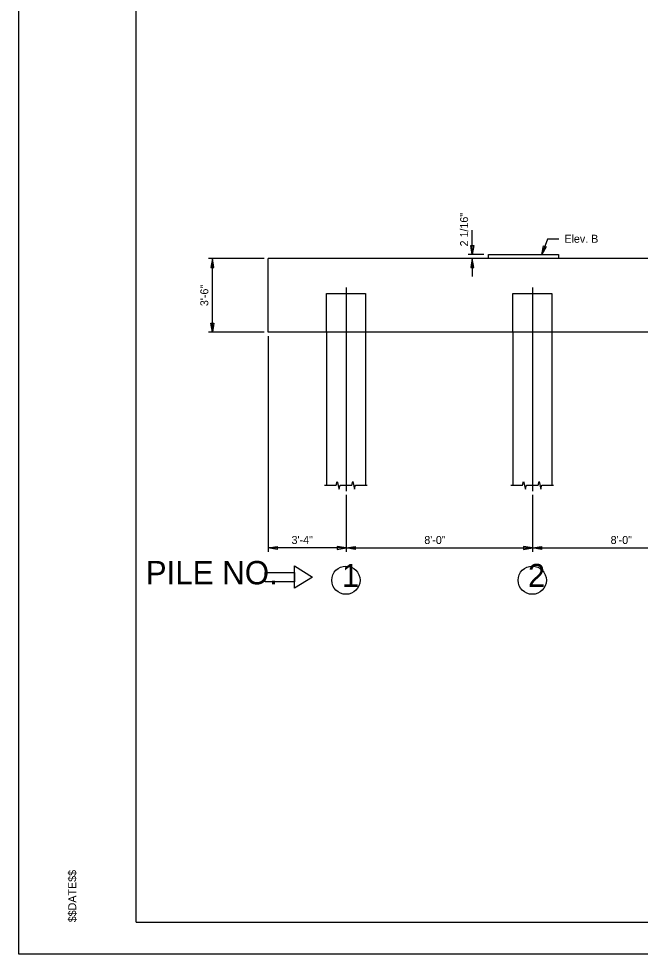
# Model space of a CAD drawing. Extents: x 437 to 537, y 571 to 720.
# Drawn here: x 437.19 to 463.88, y 654.41 to 694.6 of the extents above; entities that cross this region are included whole.
import ezdxf

# ---------------------------------------------------------------- set-up
doc = ezdxf.new("R2010")
doc.units = 0
for name, color, linetype in [('BR_AUTO DIMENSION', 7, 'Continuous'), ('BR_BORDER LINES', 7, 'Continuous'), ('BR_CENTER LINES', 7, 'Continuous'), ('BR_CONCRETE', 7, 'Continuous'), ('BR_PRESTRESSED BEAM', 7, 'Continuous'), ('BR_TABLE LINES', 7, 'Continuous'), ('BR_TEXT', 7, 'Continuous'), ('RD_SHT_IplotShp', 7, 'Continuous')]:
    doc.layers.add(name, color=color, linetype=linetype)

msp = doc.modelspace()

# ---------------------------------------------------------------- linework, layer by layer
at = {"layer": 'BR_AUTO DIMENSION'}
for p, q in [((456.66, 684.46), (456.66, 685.506)), ((456.66, 684.46), (456.595, 684.847)), ((456.595, 684.847), (456.724, 684.847)), ((456.724, 684.847), (456.66, 684.46)), ((459.897, 685.132), (459.646, 684.46)), ((459.646, 684.46), (459.721, 684.845)), ((459.721, 684.845), (459.841, 684.8)), ((460.376, 685.132), (459.897, 685.132)), ((457.157, 684.46), (456.488, 684.46)), ((459.841, 684.8), (459.646, 684.46)), ((447.732, 684.293), (445.331, 684.293)), ((445.503, 684.293), (445.438, 683.907)), ((445.503, 681.127), (445.503, 684.293)), ((445.567, 683.906), (445.503, 684.293)), ((456.66, 684.293), (456.595, 683.907)), ((456.66, 684.293), (456.66, 683.523)), ((456.724, 683.906), (456.66, 684.293)), ((445.438, 683.907), (445.567, 683.906)), ((456.595, 683.907), (456.724, 683.906)), ((445.438, 681.513), (445.567, 681.514)), ((445.503, 681.127), (445.438, 681.513)), ((445.567, 681.514), (445.503, 681.127)), ((447.732, 681.127), (445.331, 681.127)), ((447.904, 680.955), (447.904, 671.689)), ((451.242, 674.146), (451.242, 671.689)), ((459.242, 674.146), (459.242, 671.689)), ((451.242, 672.377), (451.242, 671.689)), ((447.904, 671.861), (448.291, 671.925)), ((451.237, 671.861), (447.904, 671.861)), ((448.291, 671.796), (447.904, 671.861)), ((448.291, 671.925), (448.291, 671.796)), ((451.242, 671.861), (450.855, 671.925)), ((450.855, 671.925), (450.855, 671.796)), ((450.855, 671.796), (451.242, 671.861)), ((451.237, 671.861), (459.237, 671.861)), ((451.242, 671.861), (451.629, 671.925)), ((451.629, 671.796), (451.242, 671.861)), ((451.629, 671.925), (451.629, 671.796)), ((459.242, 671.861), (458.855, 671.925)), ((458.855, 671.925), (458.855, 671.796)), ((458.855, 671.796), (459.242, 671.861)), ((459.237, 671.861), (469.571, 671.861)), ((459.242, 671.861), (459.629, 671.925)), ((459.629, 671.796), (459.242, 671.861)), ((459.629, 671.925), (459.629, 671.796))]:
    msp.add_line(p, q, dxfattribs=at)
for centre in [(451.237, 670.476), (459.237, 670.476)]:
    msp.add_circle(centre, 0.606, dxfattribs=at)
at = {"layer": 'BR_BORDER LINES'}
for p, q in [((442.23, 655.783), (442.231, 713.534)), ((442.231, 655.78), (442.231, 713.531)), ((442.23, 655.783), (534.814, 655.78)), ((442.231, 655.78), (534.814, 655.78))]:
    msp.add_line(p, q, dxfattribs=at)
at = {"layer": 'BR_CENTER LINES'}
for p, q in [((451.242, 683.043), (451.242, 681.127)), ((459.242, 683.043), (459.242, 681.127)), ((451.242, 681.127), (451.242, 674.293)), ((459.242, 681.127), (459.242, 674.293))]:
    msp.add_line(p, q, dxfattribs=at)
at = {"layer": 'BR_CONCRETE'}
for p, q in [((457.362, 684.293), (457.362, 684.46)), ((457.362, 684.46), (460.362, 684.46)), ((460.362, 684.46), (460.362, 684.293)), ((447.904, 681.127), (447.904, 684.293)), ((460.362, 684.293), (447.904, 684.293)), ((468.612, 684.293), (460.362, 684.293)), ((458.079, 681.127), (447.904, 681.127)), ((468.254, 681.127), (458.079, 681.127))]:
    msp.add_line(p, q, dxfattribs=at)
at = {"layer": 'BR_PRESTRESSED BEAM'}
for p, q in [((450.409, 681.127), (450.409, 682.793)), ((450.409, 682.793), (452.075, 682.793)), ((452.075, 682.793), (452.075, 681.127)), ((458.409, 681.127), (458.409, 682.793)), ((458.409, 682.793), (460.075, 682.793)), ((460.075, 682.793), (460.075, 681.127)), ((450.409, 681.127), (450.409, 674.551)), ((452.075, 681.127), (452.075, 674.551)), ((458.409, 681.127), (458.409, 674.551)), ((460.075, 681.127), (460.075, 674.551))]:
    msp.add_line(p, q, dxfattribs=at)
at = {"layer": 'BR_TABLE LINES'}
for points in [[(450.321, 674.551), (450.821, 674.551), (450.862, 674.718), (450.946, 674.385), (450.987, 674.551), (451.237, 674.551)], [(451.237, 674.551), (451.487, 674.551), (451.529, 674.718), (451.612, 674.385), (451.654, 674.551), (452.154, 674.551)], [(458.321, 674.551), (458.821, 674.551), (458.862, 674.718), (458.946, 674.385), (458.987, 674.551), (459.237, 674.551)], [(459.237, 674.551), (459.487, 674.551), (459.529, 674.718), (459.612, 674.385), (459.654, 674.551), (460.154, 674.551)]]:
    msp.add_lwpolyline(points, dxfattribs=at)
at = {"layer": 'BR_TEXT'}
for points in [[(447.775, 670.813), (449.037, 670.813), (449.037, 670.411), (447.775, 670.411)], [(449.037, 671.086), (449.798, 670.612), (449.037, 670.138)]]:
    msp.add_lwpolyline(points, close=True, dxfattribs=at)
at = {"layer": 'RD_SHT_IplotShp'}
msp.add_lwpolyline([(437.19, 714.906), (536.19, 714.906), (536.19, 654.406), (437.19, 654.406)], close=True, dxfattribs=at)

# ---------------------------------------------------------------- texts
at = {"layer": 'BR_TEXT'}
for s, height, rotation, p in [('2 1/16"', 0.3437, 90, (456.484, 684.813)), ('3\'-6"', 0.3438, 90, (445.331, 682.249)), ('3\'-4"', 0.3438, 360, (448.904, 672.032)), ('PILE NO.', 1.0039, 360, (442.643, 670.298)), ('$$DATE$$', 0.3437, 89.9982, (439.659, 655.78))]:
    msp.add_text(s, height=height, rotation=rotation, dxfattribs=at).set_placement(p)
for s, height, p in [('Elev. B', 0.3438, (460.617, 684.971)), ('8\'-0"', 0.3437, (454.603, 672.032)), ('8\'-0"', 0.3437, (462.603, 672.032)), ('1', 0.989, (451.07, 670.188)), ('2', 0.989, (459.054, 670.188))]:
    msp.add_text(s, height=height, dxfattribs=at).set_placement(p)

doc.saveas('drawing.dxf')
